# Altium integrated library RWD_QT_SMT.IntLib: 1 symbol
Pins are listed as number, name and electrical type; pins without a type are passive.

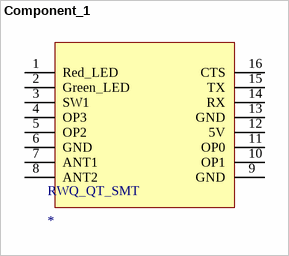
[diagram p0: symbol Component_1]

## Component_1
designator RWQ_QT_SMT
footprint PCBComponent_1
pins: 1 Red_LED, 2 Green_LED, 3 SW1, 4 OP3, 5 OP2, 6 GND, 7 ANT1, 8 ANT2, 9 GND, 10 OP1, 11 OP0, 12 5V, 13 GND, 14 RX, 15 TX, 16 CTS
